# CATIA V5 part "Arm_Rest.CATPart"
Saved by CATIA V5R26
Part number: Arm_Rest
Bounding box of the stored display mesh (mm): x 766.704 to 1406.055, y -781.992 to -669.745, z 394.638 to 524.096
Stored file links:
  D:\LinkedIn Learning\NURBS\Arm_Rest.CATPart
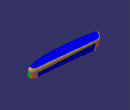
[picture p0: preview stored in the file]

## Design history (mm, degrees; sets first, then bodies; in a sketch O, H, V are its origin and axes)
AxisSystem1: origin (0, 0, 0), X (1, 0, 0), Y (0, 1, 0), Z (0, 0, 1)
Set1 "REF DATA"
  CLDGeom1 "TOP"
  CLDGeom2 "FRONT"
  CLDGeom3 "AFT_BLEND"
  CLDGeom4 "END_AFT"
  CLDGeom5 "FORWARD_BLEND"
  CLDGeom6 "BOTTOM"
  CLDGeom7 "END_FORWARD"
  CLDGeom8 "UPPER_BLENDS"
  CLDGeom9 "LOWER_BLENDS"
  DatumSurface1 "DOOR_TRIM_SURFACE"
Body1 (main body)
